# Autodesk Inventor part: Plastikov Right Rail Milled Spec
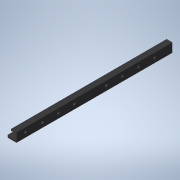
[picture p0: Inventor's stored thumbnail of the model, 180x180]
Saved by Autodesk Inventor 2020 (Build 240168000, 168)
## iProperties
Created: 2020-05
Part Number: Plastikov Right Rail Milled Spec
Material: Generic
Document SubType Name: Modeling
Designer: Iv. Tr.
Density: 1 g/cm^3
Appearance: Default
Title: D:\Downloads\Plastikov-v1-3\STEP\Plastikov Right Rail Milled Spec.stp
Author: johne
Sending System: Autodesk Inventor 2020
Preprocessor: ST-DEVELOPER v18
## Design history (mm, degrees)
feature "Solid1"
body "Solid2"
